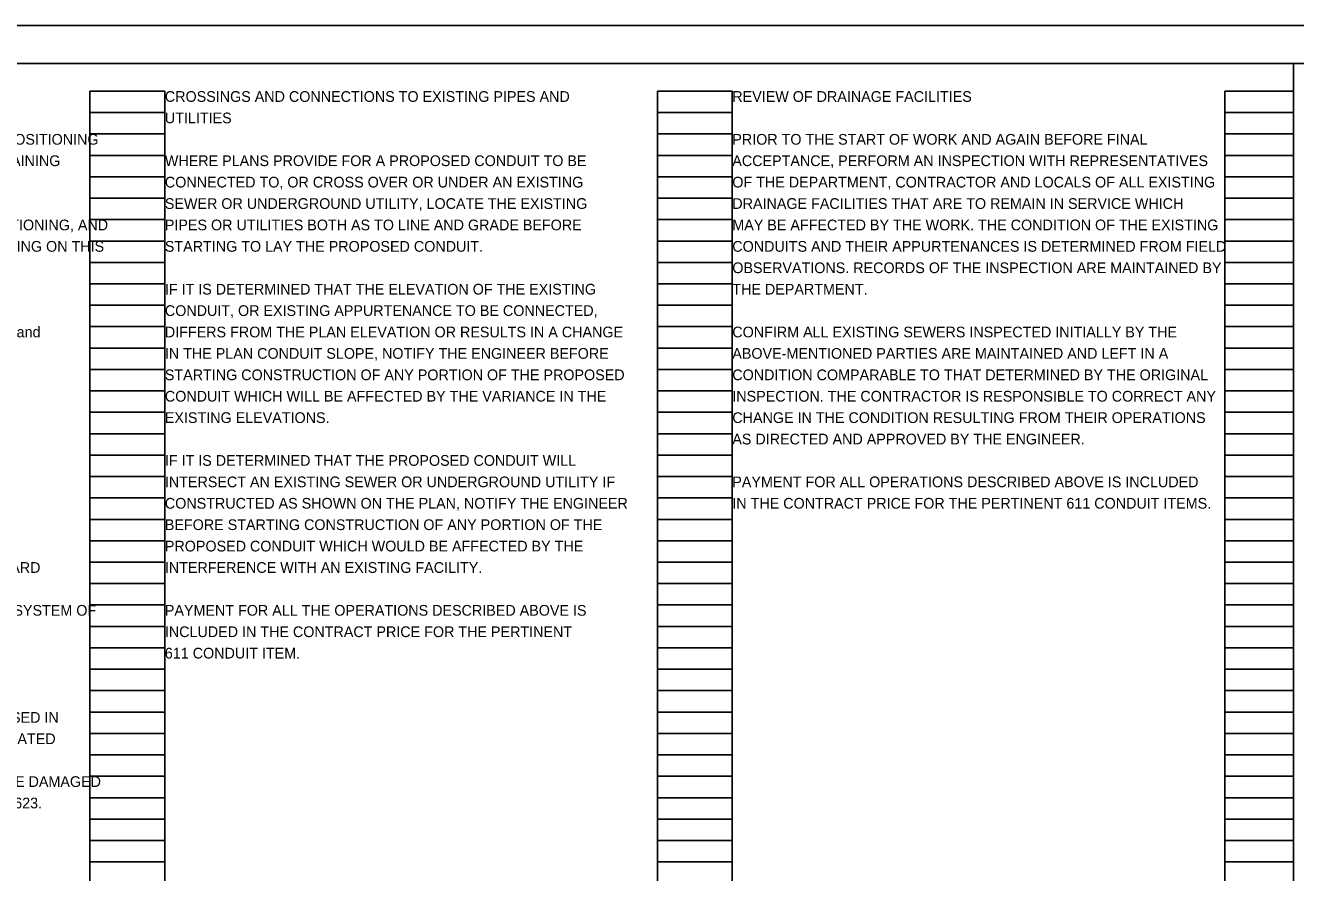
# Model space of a CAD drawing. Extents: x 0 to 42.1, y 0 to 22.
# Drawn here: x 15.42 to 32.03, y 10.92 to 22 of the extents above; entities that cross this region are included whole.
import ezdxf

# ---------------------------------------------------------------- set-up
doc = ezdxf.new("R2010")
doc.units = 0
for name, color, linetype in [('SH_Border', 7, 'Continuous'), ('SH_Cut_Line', 7, 'Continuous'), ('SH_Data', 7, 'Continuous'), ('SH_Text', 7, 'Continuous')]:
    doc.layers.add(name, color=color, linetype=linetype)

msp = doc.modelspace()

# ---------------------------------------------------------------- linework, layer by layer
at = {"layer": 'SH_Border'}
msp.add_line((32, 0.5), (32, 21.5), dxfattribs=at)
msp.add_lwpolyline([(1.5, 21.5), (33.5, 21.5), (33.5, 0.5), (1.5, 0.5)], close=True, dxfattribs=at)
at = {"layer": 'SH_Cut_Line'}
msp.add_lwpolyline([(0, 0), (34, 0), (34, 22), (0, 22)], close=True, dxfattribs=at)
at = {"layer": 'SH_Data'}
for p, q in [((16.26, 0.98), (16.26, 21.14)), ((16.26, 21.14), (17.24, 21.14)), ((17.24, 0.98), (17.24, 21.14)), ((23.68, 0.98), (23.68, 21.14)), ((23.68, 21.14), (24.66, 21.14)), ((24.66, 0.98), (24.66, 21.14)), ((31.1, 0.98), (31.1, 21.14)), ((31.1, 21.14), (32, 21.14)), ((32, 0.98), (32, 21.14)), ((16.26, 20.86), (17.24, 20.86)), ((23.68, 20.86), (24.66, 20.86)), ((31.1, 20.86), (32, 20.86)), ((16.26, 20.58), (17.24, 20.58)), ((23.68, 20.58), (24.66, 20.58)), ((31.1, 20.58), (32, 20.58)), ((16.26, 20.3), (17.24, 20.3)), ((23.68, 20.3), (24.66, 20.3)), ((31.1, 20.3), (32, 20.3)), ((16.26, 20.02), (17.24, 20.02)), ((23.68, 20.02), (24.66, 20.02)), ((31.1, 20.02), (32, 20.02)), ((16.26, 19.74), (17.24, 19.74)), ((23.68, 19.74), (24.66, 19.74)), ((31.1, 19.74), (32, 19.74)), ((16.26, 19.46), (17.24, 19.46)), ((23.68, 19.46), (24.66, 19.46)), ((31.1, 19.46), (32, 19.46)), ((16.26, 19.18), (17.24, 19.18)), ((23.68, 19.18), (24.66, 19.18)), ((31.1, 19.18), (32, 19.18)), ((16.26, 18.9), (17.24, 18.9)), ((23.68, 18.9), (24.66, 18.9)), ((31.1, 18.9), (32, 18.9)), ((16.26, 18.62), (17.24, 18.62)), ((23.68, 18.62), (24.66, 18.62)), ((31.1, 18.62), (32, 18.62)), ((16.26, 18.34), (17.24, 18.34)), ((23.68, 18.34), (24.66, 18.34)), ((31.1, 18.34), (32, 18.34)), ((16.26, 18.06), (17.24, 18.06)), ((23.68, 18.06), (24.66, 18.06)), ((31.1, 18.06), (32, 18.06)), ((16.26, 17.78), (17.24, 17.78)), ((23.68, 17.78), (24.66, 17.78)), ((31.1, 17.78), (32, 17.78)), ((16.26, 17.5), (17.24, 17.5)), ((23.68, 17.5), (24.66, 17.5)), ((31.1, 17.5), (32, 17.5)), ((16.26, 17.22), (17.24, 17.22)), ((23.68, 17.22), (24.66, 17.22)), ((31.1, 17.22), (32, 17.22)), ((16.26, 16.94), (17.24, 16.94)), ((23.68, 16.94), (24.66, 16.94)), ((31.1, 16.94), (32, 16.94)), ((16.26, 16.66), (17.24, 16.66)), ((23.68, 16.66), (24.66, 16.66)), ((31.1, 16.66), (32, 16.66)), ((16.26, 16.38), (17.24, 16.38)), ((23.68, 16.38), (24.66, 16.38)), ((31.1, 16.38), (32, 16.38)), ((16.26, 16.1), (17.24, 16.1)), ((23.68, 16.1), (24.66, 16.1)), ((31.1, 16.1), (32, 16.1)), ((16.26, 15.82), (17.24, 15.82)), ((23.68, 15.82), (24.66, 15.82)), ((31.1, 15.82), (32, 15.82)), ((16.26, 15.54), (17.24, 15.54)), ((23.68, 15.54), (24.66, 15.54)), ((31.1, 15.54), (32, 15.54)), ((16.26, 15.26), (17.24, 15.26)), ((23.68, 15.26), (24.66, 15.26)), ((31.1, 15.26), (32, 15.26)), ((16.26, 14.98), (17.24, 14.98)), ((23.68, 14.98), (24.66, 14.98)), ((31.1, 14.98), (32, 14.98)), ((16.26, 14.7), (17.24, 14.7)), ((23.68, 14.7), (24.66, 14.7)), ((31.1, 14.7), (32, 14.7)), ((16.26, 14.42), (17.24, 14.42)), ((23.68, 14.42), (24.66, 14.42)), ((31.1, 14.42), (32, 14.42)), ((16.26, 14.14), (17.24, 14.14)), ((23.68, 14.14), (24.66, 14.14)), ((31.1, 14.14), (32, 14.14)), ((16.26, 13.86), (17.24, 13.86)), ((23.68, 13.86), (24.66, 13.86)), ((31.1, 13.86), (32, 13.86)), ((16.26, 13.58), (17.24, 13.58)), ((23.68, 13.58), (24.66, 13.58)), ((31.1, 13.58), (32, 13.58)), ((16.26, 13.3), (17.24, 13.3)), ((23.68, 13.3), (24.66, 13.3)), ((31.1, 13.3), (32, 13.3)), ((16.26, 13.02), (17.24, 13.02)), ((23.68, 13.02), (24.66, 13.02)), ((31.1, 13.02), (32, 13.02)), ((16.26, 12.74), (17.24, 12.74)), ((23.68, 12.74), (24.66, 12.74)), ((31.1, 12.74), (32, 12.74)), ((16.26, 12.46), (17.24, 12.46)), ((23.68, 12.46), (24.66, 12.46)), ((31.1, 12.46), (32, 12.46)), ((16.26, 12.18), (17.24, 12.18)), ((23.68, 12.18), (24.66, 12.18)), ((31.1, 12.18), (32, 12.18)), ((16.26, 11.9), (17.24, 11.9)), ((23.68, 11.9), (24.66, 11.9)), ((31.1, 11.9), (32, 11.9)), ((16.26, 11.62), (17.24, 11.62)), ((23.68, 11.62), (24.66, 11.62)), ((31.1, 11.62), (32, 11.62)), ((16.26, 11.34), (17.24, 11.34)), ((23.68, 11.34), (24.66, 11.34)), ((31.1, 11.34), (32, 11.34)), ((16.26, 11.06), (17.24, 11.06)), ((23.68, 11.06), (24.66, 11.06)), ((31.1, 11.06), (32, 11.06))]:
    msp.add_line(p, q, dxfattribs=at)

# ---------------------------------------------------------------- texts
at = {"layer": 'SH_Text'}
for s, p in [('CROSSINGS AND CONNECTIONS TO EXISTING PIPES AND', (17.24, 21)), ('REVIEW OF DRAINAGE FACILITIES', (24.66, 21)), ('UTILITIES', (17.24, 20.72)), ('PRIMARY PROJECT CONTROL MONUMENTS GOVERN ALL POSITIONING ', (9.82, 20.44)), ('PRIOR TO THE START OF WORK AND AGAIN BEFORE FINAL', (24.66, 20.44)), ('ON ODOT PROJECTS. SEE THIS SHEET FOR A TABLE CONTAINING ', (9.82, 20.16)), ('WHERE PLANS PROVIDE FOR A PROPOSED CONDUIT TO BE', (17.24, 20.16)), ('ACCEPTANCE, PERFORM AN INSPECTION WITH REPRESENTATIVES', (24.66, 20.16)), ('CONNECTED TO, OR CROSS OVER OR UNDER AN EXISTING', (17.24, 19.88)), ('OF THE DEPARTMENT, CONTRACTOR AND LOCALS OF ALL EXISTING', (24.66, 19.88)), ('SEWER OR UNDERGROUND UTILITY, LOCATE THE EXISTING', (17.24, 19.6)), ('DRAINAGE FACILITIES THAT ARE TO REMAIN IN SERVICE WHICH', (24.66, 19.6)), ('USE THE FOLLOWING PROJECT CONTROL, VERTICAL POSITIONING, AND ', (9.82, 19.32)), ('PIPES OR UTILITIES BOTH AS TO LINE AND GRADE BEFORE', (17.24, 19.32)), ('MAY BE AFFECTED BY THE WORK. THE CONDITION OF THE EXISTING', (24.66, 19.32)), ('HORIZONTAL POSITIONING PARAMETERS FOR ALL SURVEYING ON THIS ', (9.82, 19.04)), ('STARTING TO LAY THE PROPOSED CONDUIT.', (17.24, 19.04)), ('CONDUITS AND THEIR APPURTENANCES IS DETERMINED FROM FIELD', (24.66, 19.04)), ('OBSERVATIONS. RECORDS OF THE INSPECTION ARE MAINTAINED BY', (24.66, 18.76)), ('IF IT IS DETERMINED THAT THE ELEVATION OF THE EXISTING', (17.24, 18.48)), ('THE DEPARTMENT.', (24.66, 18.48)), ('CONDUIT, OR EXISTING APPURTENANCE TO BE CONNECTED,', (17.24, 18.2)), ('POSITIONING METHOD:  ODOT REAL TIME NETWORK (2011) and ', (9.82, 17.92)), ('DIFFERS FROM THE PLAN ELEVATION OR RESULTS IN A CHANGE', (17.24, 17.92)), ('CONFIRM ALL EXISTING SEWERS INSPECTED INITIALLY BY THE', (24.66, 17.92)), ('IN THE PLAN CONDUIT SLOPE, NOTIFY THE ENGINEER BEFORE', (17.24, 17.64)), ('ABOVE-MENTIONED PARTIES ARE MAINTAINED AND LEFT IN A', (24.66, 17.64)), ('STARTING CONSTRUCTION OF ANY PORTION OF THE PROPOSED', (17.24, 17.36)), ('CONDITION COMPARABLE TO THAT DETERMINED BY THE ORIGINAL', (24.66, 17.36)), ('CONDUIT WHICH WILL BE AFFECTED BY THE VARIANCE IN THE', (17.24, 17.08)), ('INSPECTION. THE CONTRACTOR IS RESPONSIBLE TO CORRECT ANY', (24.66, 17.08)), ('EXISTING ELEVATIONS.', (17.24, 16.8)), ('CHANGE IN THE CONDITION RESULTING FROM THEIR OPERATIONS', (24.66, 16.8)), ('AS DIRECTED AND APPROVED BY THE ENGINEER.', (24.66, 16.52)), ('IF IT IS DETERMINED THAT THE PROPOSED CONDUIT WILL', (17.24, 16.24)), ('INTERSECT AN EXISTING SEWER OR UNDERGROUND UTILITY IF', (17.24, 15.96)), ('PAYMENT FOR ALL OPERATIONS DESCRIBED ABOVE IS INCLUDED', (24.66, 15.96)), ('CONSTRUCTED AS SHOWN ON THE PLAN, NOTIFY THE ENGINEER', (17.24, 15.68)), ('IN THE CONTRACT PRICE FOR THE PERTINENT 611 CONDUIT ITEMS.', (24.66, 15.68)), ('BEFORE STARTING CONSTRUCTION OF ANY PORTION OF THE', (17.24, 15.4)), ('PROPOSED CONDUIT WHICH WOULD BE AFFECTED BY THE', (17.24, 15.12)), ('MAP PROJECTION: LAMBERT CONFORMAL CONIC 2 STANDARD ', (9.82, 14.84)), ('INTERFERENCE WITH AN EXISTING FACILITY.', (17.24, 14.84)), ('COORDINATE SYSTEM:  OHIO STATE PLANE CO-ORDINATE SYSTEM OF ', (9.82, 14.28)), ('PAYMENT FOR ALL THE OPERATIONS DESCRIBED ABOVE IS', (17.24, 14.28)), ('INCLUDED IN THE CONTRACT PRICE FOR THE PERTINENT', (17.24, 14)), ('611 CONDUIT ITEM.', (17.24, 13.72)), ('USE THE POSITIONING METHODS AND MONUMENT TYPE USED IN', (9.82, 12.88)), ('THE ORIGINAL SURVEY TO RESTORE ALL MONUMENTS RELATED', (9.82, 12.6)), ('DESTROYED BY CONSTRUCTION ACTIVITIES.  RESTORE THE DAMAGED', (9.82, 12.04)), ('OR DESTROYED MONUMENTS IN ACCORDANCE WITH CMS 623.', (9.82, 11.76))]:
    msp.add_text(s, height=0.14, dxfattribs=at).set_placement(p)

doc.saveas('drawing.dxf')
